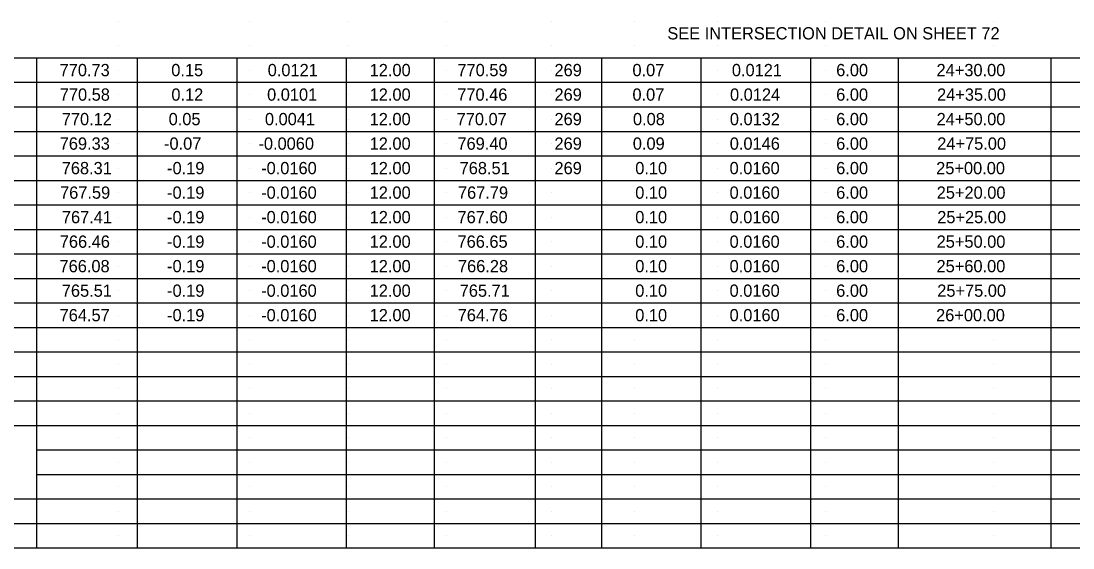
# Model space of a CAD drawing. Extents: x -15.4 to 18.6, y -12.6 to 9.4.
# Drawn here: x -8.3 to 3.72, y -5.11 to 0.91 of the extents above; entities that cross this region are included whole.
import ezdxf

# ---------------------------------------------------------------- set-up
doc = ezdxf.new("R2010")
doc.units = 0
doc.layers.add('SH_Data', color=7, linetype='Continuous')
doc.layers.add('SH_Text', color=7, linetype='Continuous')

msp = doc.modelspace()

# ---------------------------------------------------------------- linework, layer by layer
at = {"layer": 'SH_Data'}
for p, q in [((-7.182, 0.908), (-7.182, 0.908)), ((-5.682, 0.908), (-5.682, 0.908)), ((-4.557, 0.908), (-4.557, 0.908)), ((-3.432, 0.908), (-3.432, 0.908)), ((-2.232, 0.908), (-2.232, 0.908)), ((-1.282, 0.908), (-1.282, 0.908)), ((-0.332, 0.908), (-0.332, 0.908)), ((0.893, 0.908), (0.893, 0.908)), ((2.818, 0.908), (2.818, 0.908)), ((-7.182, 0.628), (-7.182, 0.628)), ((-5.682, 0.628), (-5.682, 0.628)), ((-4.557, 0.628), (-4.557, 0.628)), ((-3.432, 0.628), (-3.432, 0.628)), ((-2.232, 0.628), (-2.232, 0.628)), ((-1.282, 0.628), (-1.282, 0.628)), ((-0.332, 0.628), (-0.332, 0.628)), ((0.893, 0.628), (0.893, 0.628)), ((2.818, 0.628), (2.818, 0.628)), ((-12.667, 0.488), (15.877, 0.488)), ((-8.121, 0.488), (-8.121, -5.112)), ((-6.968, 0.488), (-6.968, -5.112)), ((-5.831, 0.488), (-5.831, -5.112)), ((-4.58, 0.488), (-4.58, -5.112)), ((-3.575, 0.488), (-3.575, -5.112)), ((-2.422, 0.488), (-2.422, -5.112)), ((-1.664, 0.488), (-1.664, -5.112)), ((-0.528, 0.488), (-0.528, -5.112)), ((0.724, 0.488), (0.724, -5.112)), ((1.729, 0.488), (1.729, -5.112)), ((3.474, 0.488), (3.474, -5.112)), ((-7.182, 0.348), (-7.182, 0.348)), ((-5.682, 0.348), (-5.682, 0.348)), ((-4.557, 0.348), (-4.557, 0.348)), ((-3.432, 0.348), (-3.432, 0.348)), ((-2.232, 0.348), (-2.232, 0.348)), ((-1.282, 0.348), (-1.282, 0.348)), ((-0.332, 0.348), (-0.332, 0.348)), ((0.893, 0.348), (0.893, 0.348)), ((2.818, 0.348), (2.818, 0.348)), ((-12.667, 0.208), (15.877, 0.208)), ((-7.182, 0.068), (-7.182, 0.068)), ((-5.682, 0.068), (-5.682, 0.068)), ((-4.557, 0.068), (-4.557, 0.068)), ((-3.432, 0.068), (-3.432, 0.068)), ((-2.232, 0.068), (-2.232, 0.068)), ((-1.282, 0.068), (-1.282, 0.068)), ((-0.332, 0.068), (-0.332, 0.068)), ((0.893, 0.068), (0.893, 0.068)), ((2.818, 0.068), (2.818, 0.068)), ((-12.667, -0.072), (15.877, -0.072)), ((-7.182, -0.212), (-7.182, -0.212)), ((-5.682, -0.212), (-5.682, -0.212)), ((-4.557, -0.212), (-4.557, -0.212)), ((-3.432, -0.212), (-3.432, -0.212)), ((-2.232, -0.212), (-2.232, -0.212)), ((-1.282, -0.212), (-1.282, -0.212)), ((-0.332, -0.212), (-0.332, -0.212)), ((0.893, -0.212), (0.893, -0.212)), ((2.818, -0.212), (2.818, -0.212)), ((-12.667, -0.352), (15.877, -0.352)), ((-7.182, -0.492), (-7.182, -0.492)), ((-5.682, -0.492), (-5.682, -0.492)), ((-4.557, -0.492), (-4.557, -0.492)), ((-3.432, -0.492), (-3.432, -0.492)), ((-2.232, -0.492), (-2.232, -0.492)), ((-1.282, -0.492), (-1.282, -0.492)), ((-0.332, -0.492), (-0.332, -0.492)), ((0.893, -0.492), (0.893, -0.492)), ((2.818, -0.492), (2.818, -0.492)), ((-12.667, -0.632), (15.877, -0.632)), ((-7.182, -0.772), (-7.182, -0.772)), ((-5.682, -0.772), (-5.682, -0.772)), ((-4.557, -0.772), (-4.557, -0.772)), ((-3.432, -0.772), (-3.432, -0.772)), ((-2.232, -0.772), (-2.232, -0.772)), ((-1.282, -0.772), (-1.282, -0.772)), ((-0.332, -0.772), (-0.332, -0.772)), ((0.893, -0.772), (0.893, -0.772)), ((2.818, -0.772), (2.818, -0.772)), ((-12.667, -0.912), (15.877, -0.912)), ((-7.182, -1.052), (-7.182, -1.052)), ((-5.682, -1.052), (-5.682, -1.052)), ((-4.557, -1.052), (-4.557, -1.052)), ((-3.432, -1.052), (-3.432, -1.052)), ((-2.232, -1.052), (-2.232, -1.052)), ((-1.282, -1.052), (-1.282, -1.052)), ((-0.332, -1.052), (-0.332, -1.052)), ((0.893, -1.052), (0.893, -1.052)), ((2.818, -1.052), (2.818, -1.052)), ((-12.667, -1.192), (15.877, -1.192)), ((-7.182, -1.332), (-7.182, -1.332)), ((-5.682, -1.332), (-5.682, -1.332)), ((-4.557, -1.332), (-4.557, -1.332)), ((-3.432, -1.332), (-3.432, -1.332)), ((-2.232, -1.332), (-2.232, -1.332)), ((-1.282, -1.332), (-1.282, -1.332)), ((-0.332, -1.332), (-0.332, -1.332)), ((0.893, -1.332), (0.893, -1.332)), ((2.818, -1.332), (2.818, -1.332)), ((-12.667, -1.472), (15.877, -1.472)), ((-7.182, -1.612), (-7.182, -1.612)), ((-5.682, -1.612), (-5.682, -1.612)), ((-4.557, -1.612), (-4.557, -1.612)), ((-3.432, -1.612), (-3.432, -1.612)), ((-2.232, -1.612), (-2.232, -1.612)), ((-1.282, -1.612), (-1.282, -1.612)), ((-0.332, -1.612), (-0.332, -1.612)), ((0.893, -1.612), (0.893, -1.612)), ((2.818, -1.612), (2.818, -1.612)), ((-12.667, -1.752), (15.877, -1.752)), ((-7.182, -1.892), (-7.182, -1.892)), ((-5.682, -1.892), (-5.682, -1.892)), ((-4.557, -1.892), (-4.557, -1.892)), ((-3.432, -1.892), (-3.432, -1.892)), ((-2.232, -1.892), (-2.232, -1.892)), ((-1.282, -1.892), (-1.282, -1.892)), ((-0.332, -1.892), (-0.332, -1.892)), ((0.893, -1.892), (0.893, -1.892)), ((2.818, -1.892), (2.818, -1.892)), ((-12.667, -2.032), (15.877, -2.032)), ((-7.182, -2.172), (-7.182, -2.172)), ((-5.682, -2.172), (-5.682, -2.172)), ((-4.557, -2.172), (-4.557, -2.172)), ((-3.432, -2.172), (-3.432, -2.172)), ((-2.232, -2.172), (-2.232, -2.172)), ((-1.282, -2.172), (-1.282, -2.172)), ((-0.332, -2.172), (-0.332, -2.172)), ((0.893, -2.172), (0.893, -2.172)), ((2.818, -2.172), (2.818, -2.172)), ((-12.667, -2.312), (15.877, -2.312)), ((-7.182, -2.452), (-7.182, -2.452)), ((-5.682, -2.452), (-5.682, -2.452)), ((-4.557, -2.452), (-4.557, -2.452)), ((-3.432, -2.452), (-3.432, -2.452)), ((-2.232, -2.452), (-2.232, -2.452)), ((-1.282, -2.452), (-1.282, -2.452)), ((-0.332, -2.452), (-0.332, -2.452)), ((0.893, -2.452), (0.893, -2.452)), ((2.818, -2.452), (2.818, -2.452)), ((-12.667, -2.592), (15.877, -2.592)), ((-7.182, -2.732), (-7.182, -2.732)), ((-5.682, -2.732), (-5.682, -2.732)), ((-4.557, -2.732), (-4.557, -2.732)), ((-3.432, -2.732), (-3.432, -2.732)), ((-2.232, -2.732), (-2.232, -2.732)), ((-1.282, -2.732), (-1.282, -2.732)), ((-0.332, -2.732), (-0.332, -2.732)), ((0.893, -2.732), (0.893, -2.732)), ((2.818, -2.732), (2.818, -2.732)), ((-12.667, -2.872), (15.877, -2.872)), ((-7.182, -3.012), (-7.182, -3.012)), ((-5.682, -3.012), (-5.682, -3.012)), ((-4.557, -3.012), (-4.557, -3.012)), ((-3.432, -3.012), (-3.432, -3.012)), ((-2.232, -3.012), (-2.232, -3.012)), ((-1.282, -3.012), (-1.282, -3.012)), ((-0.332, -3.012), (-0.332, -3.012)), ((0.893, -3.012), (0.893, -3.012)), ((2.818, -3.012), (2.818, -3.012)), ((-12.667, -3.152), (15.877, -3.152)), ((-7.182, -3.292), (-7.182, -3.292)), ((-5.682, -3.292), (-5.682, -3.292)), ((-4.557, -3.292), (-4.557, -3.292)), ((-3.432, -3.292), (-3.432, -3.292)), ((-2.232, -3.292), (-2.232, -3.292)), ((-1.282, -3.292), (-1.282, -3.292)), ((-0.332, -3.292), (-0.332, -3.292)), ((0.893, -3.292), (0.893, -3.292)), ((2.818, -3.292), (2.818, -3.292)), ((-12.667, -3.432), (15.877, -3.432)), ((-7.182, -3.572), (-7.182, -3.572)), ((-5.682, -3.572), (-5.682, -3.572)), ((-4.557, -3.572), (-4.557, -3.572)), ((-3.432, -3.572), (-3.432, -3.572)), ((-2.232, -3.572), (-2.232, -3.572)), ((-1.282, -3.572), (-1.282, -3.572)), ((-0.332, -3.572), (-0.332, -3.572)), ((0.893, -3.572), (0.893, -3.572)), ((2.818, -3.572), (2.818, -3.572)), ((-12.667, -3.712), (15.877, -3.712)), ((-7.182, -3.852), (-7.182, -3.852)), ((-5.682, -3.852), (-5.682, -3.852)), ((-4.557, -3.852), (-4.557, -3.852)), ((-3.432, -3.852), (-3.432, -3.852)), ((-2.232, -3.852), (-2.232, -3.852)), ((-1.282, -3.852), (-1.282, -3.852)), ((-0.332, -3.852), (-0.332, -3.852)), ((0.893, -3.852), (0.893, -3.852)), ((2.818, -3.852), (2.818, -3.852)), ((-8.121, -3.992), (15.877, -3.992)), ((-7.182, -4.132), (-7.182, -4.132)), ((-5.682, -4.132), (-5.682, -4.132)), ((-4.557, -4.132), (-4.557, -4.132)), ((-3.432, -4.132), (-3.432, -4.132)), ((-2.232, -4.132), (-2.232, -4.132)), ((-1.282, -4.132), (-1.282, -4.132)), ((-0.332, -4.132), (-0.332, -4.132)), ((0.893, -4.132), (0.893, -4.132)), ((2.818, -4.132), (2.818, -4.132)), ((-8.121, -4.272), (15.877, -4.272)), ((-7.182, -4.412), (-7.182, -4.412)), ((-5.682, -4.412), (-5.682, -4.412)), ((-4.557, -4.412), (-4.557, -4.412)), ((-3.432, -4.412), (-3.432, -4.412)), ((-2.232, -4.412), (-2.232, -4.412)), ((-1.282, -4.412), (-1.282, -4.412)), ((-0.332, -4.412), (-0.332, -4.412)), ((0.893, -4.412), (0.893, -4.412)), ((2.818, -4.412), (2.818, -4.412)), ((-12.667, -4.552), (15.877, -4.552)), ((-7.182, -4.692), (-7.182, -4.692)), ((-5.682, -4.692), (-5.682, -4.692)), ((-4.557, -4.692), (-4.557, -4.692)), ((-3.432, -4.692), (-3.432, -4.692)), ((-2.232, -4.692), (-2.232, -4.692)), ((-1.282, -4.692), (-1.282, -4.692)), ((-0.332, -4.692), (-0.332, -4.692)), ((0.893, -4.692), (0.893, -4.692)), ((2.818, -4.692), (2.818, -4.692)), ((-12.667, -4.832), (15.877, -4.832)), ((-7.182, -4.972), (-7.182, -4.972)), ((-5.682, -4.972), (-5.682, -4.972)), ((-4.557, -4.972), (-4.557, -4.972)), ((-3.432, -4.972), (-3.432, -4.972)), ((-2.232, -4.972), (-2.232, -4.972)), ((-1.282, -4.972), (-1.282, -4.972)), ((-0.332, -4.972), (-0.332, -4.972)), ((0.893, -4.972), (0.893, -4.972)), ((2.818, -4.972), (2.818, -4.972)), ((-12.667, -5.112), (15.877, -5.112))]:
    msp.add_line(p, q, dxfattribs=at)

# ---------------------------------------------------------------- texts
at = {"layer": 'SH_Text'}
for s, p in [('SEE INTERSECTION DETAIL ON SHEET 72', (-0.91, 0.698)), ('770.73', (-7.855, 0.278)), ('0.15', (-6.579, 0.278)), ('0.0121', (-5.477, 0.278)), ('12.00', (-4.312, 0.278)), ('770.59', (-3.309, 0.278)), ('269', (-2.2, 0.278)), ('0.07', (-1.309, 0.278)), ('0.0121', (-0.173, 0.278)), ('6.00', (1.019, 0.278)), ('24+30.00', (2.166, 0.278)), ('770.58', (-7.853, -0.002)), ('0.12', (-6.578, -0.002)), ('0.0101', (-5.484, -0.002)), ('12.00', (-4.312, -0.002)), ('770.46', (-3.311, -0.002)), ('269', (-2.2, -0.002)), ('0.07', (-1.309, -0.002)), ('0.0124', (-0.194, -0.002)), ('6.00', (1.019, -0.002)), ('24+35.00', (2.172, -0.002)), ('770.12', (-7.83, -0.282)), ('0.05', (-6.609, -0.282)), ('0.0041', (-5.509, -0.282)), ('12.00', (-4.312, -0.282)), ('770.07', (-3.318, -0.282)), ('269', (-2.2, -0.282)), ('0.08', (-1.303, -0.282)), ('0.0132', (-0.196, -0.282)), ('6.00', (1.019, -0.282)), ('24+50.00', (2.167, -0.282)), ('769.33', (-7.854, -0.562)), ('-0.07', (-6.662, -0.562)), ('-0.0060', (-5.583, -0.562)), ('12.00', (-4.312, -0.562)), ('769.40', (-3.309, -0.562)), ('269', (-2.2, -0.562)), ('0.09', (-1.305, -0.562)), ('0.0146', (-0.197, -0.562)), ('6.00', (1.019, -0.562)), ('24+75.00', (2.174, -0.562)), ('768.31', (-7.831, -0.842)), ('-0.19', (-6.627, -0.842)), ('-0.0160', (-5.552, -0.842)), ('12.00', (-4.312, -0.842)), ('768.51', (-3.284, -0.842)), ('269', (-2.2, -0.842)), ('0.10', (-1.277, -0.842)), ('0.0160', (-0.199, -0.842)), ('6.00', (1.019, -0.842)), ('25+00.00', (2.162, -0.842)), ('767.59', (-7.85, -1.122)), ('-0.19', (-6.627, -1.122)), ('-0.0160', (-5.552, -1.122)), ('12.00', (-4.312, -1.122)), ('767.79', (-3.303, -1.122)), ('0.10', (-1.277, -1.122)), ('0.0160', (-0.199, -1.122)), ('6.00', (1.019, -1.122)), ('25+20.00', (2.168, -1.122)), ('767.41', (-7.829, -1.402)), ('-0.19', (-6.627, -1.402)), ('-0.0160', (-5.552, -1.402)), ('12.00', (-4.312, -1.402)), ('767.60', (-3.308, -1.402)), ('0.10', (-1.277, -1.402)), ('0.0160', (-0.199, -1.402)), ('6.00', (1.019, -1.402)), ('25+25.00', (2.174, -1.402)), ('766.46', (-7.853, -1.682)), ('-0.19', (-6.627, -1.682)), ('-0.0160', (-5.552, -1.682)), ('12.00', (-4.312, -1.682)), ('766.65', (-3.308, -1.682)), ('0.10', (-1.277, -1.682)), ('0.0160', (-0.199, -1.682)), ('6.00', (1.019, -1.682)), ('25+50.00', (2.167, -1.682)), ('766.08', (-7.856, -1.962)), ('-0.19', (-6.627, -1.962)), ('-0.0160', (-5.552, -1.962)), ('12.00', (-4.312, -1.962)), ('766.28', (-3.303, -1.962)), ('0.10', (-1.277, -1.962)), ('0.0160', (-0.199, -1.962)), ('6.00', (1.019, -1.962)), ('25+60.00', (2.166, -1.962)), ('765.51', (-7.83, -2.242)), ('-0.19', (-6.627, -2.242)), ('-0.0160', (-5.552, -2.242)), ('12.00', (-4.312, -2.242)), ('765.71', (-3.283, -2.242)), ('0.10', (-1.277, -2.242)), ('0.0160', (-0.199, -2.242)), ('6.00', (1.019, -2.242)), ('25+75.00', (2.174, -2.242)), ('764.57', (-7.855, -2.522)), ('-0.19', (-6.627, -2.522)), ('-0.0160', (-5.552, -2.522)), ('12.00', (-4.312, -2.522)), ('764.76', (-3.306, -2.522)), ('0.10', (-1.277, -2.522)), ('0.0160', (-0.199, -2.522)), ('6.00', (1.019, -2.522)), ('26+00.00', (2.161, -2.522))]:
    msp.add_text(s, height=0.14, dxfattribs=at).set_placement(p)

doc.saveas('drawing.dxf')
